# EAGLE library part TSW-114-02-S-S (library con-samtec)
THROUGH-HOLE .025" SQ POST HEADER Source: Samtec TSW.pdf
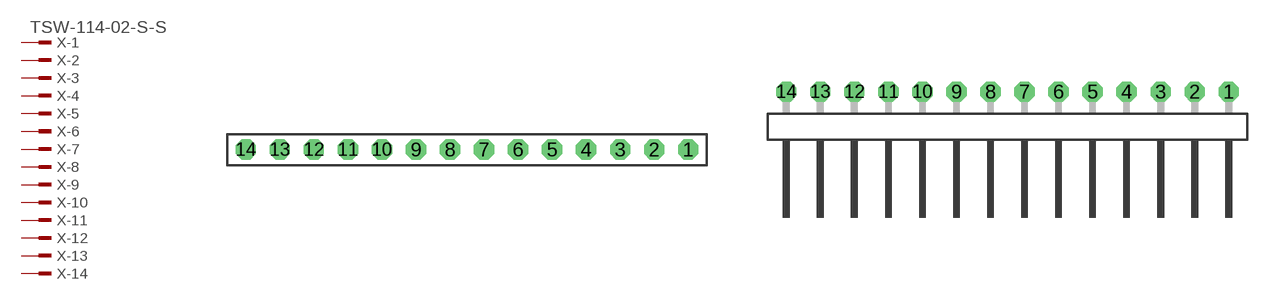
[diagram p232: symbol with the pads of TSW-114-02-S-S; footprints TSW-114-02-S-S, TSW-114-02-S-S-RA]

Designator prefix X; gates -1=MPINV -2=MPIN -3=MPIN -4=MPIN -5=MPIN -6=MPIN -7=MPIN -8=MPIN -9=MPIN -10=MPIN -11=MPIN -12=MPIN -13=MPIN -14=MPIN

## TSW-114-02-S-S (OC_FARNELL: unknown; OC_NEWARK: unknown)  [TSW-114-02-S-S]
1  -1:1  pas
2  -2:1  pas
3  -3:1  pas
4  -4:1  pas
5  -5:1  pas
6  -6:1  pas
7  -7:1  pas
8  -8:1  pas
9  -9:1  pas
10  -10:1  pas
11  -11:1  pas
12  -12:1  pas
13  -13:1  pas
14  -14:1  pas

## TSW-114-02-S-S-RA (OC_FARNELL: unknown; OC_NEWARK: unknown)  [TSW-114-02-S-S-RA]
Pads as for TSW-114-02-S-S

## Footprint TSW-114-02-S-S (pad centres in mm)
THROUGH-HOLE .025" SQ POST HEADER Source: Samtec TSW.pdf
drill 1 pad 1.5 octagon: 1 16.51,0; 2 13.97,0; 3 11.43,0; 4 8.89,0; 5 6.35,0; 6 3.81,0; 7 1.27,0; 8 -1.27,0; 9 -3.81,0; 10 -6.35,0; 11 -8.89,0; 12 -11.43,0; 13 -13.97,0; 14 -16.51,0

## Footprint TSW-114-02-S-S-RA (pad centres in mm)
THROUGH-HOLE .025" SQ POST HEADER Source: Samtec TSW.pdf
drill 1 pad 1.5 octagon: 1 16.51,1.524; 2 13.97,1.524; 3 11.43,1.524; 4 8.89,1.524; 5 6.35,1.524; 6 3.81,1.524; 7 1.27,1.524; 8 -1.27,1.524; 9 -3.81,1.524; 10 -6.35,1.524; 11 -8.89,1.524; 12 -11.43,1.524; 13 -13.97,1.524; 14 -16.51,1.524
